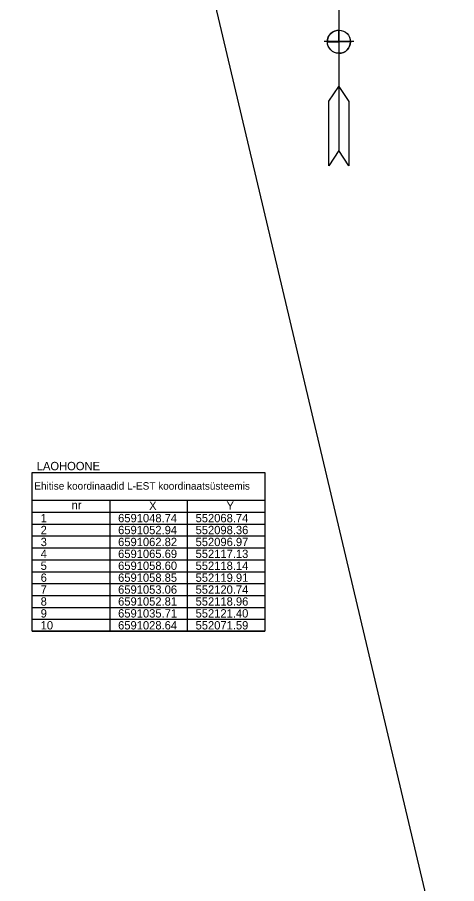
# Model space of a CAD drawing. Extents: x 551828 to 552309, y 6590593 to 6591152.
# Drawn here: x 552174 to 552210.9, y 6591016.3 to 6591089 of the extents above; entities that cross this region are included whole.
import ezdxf

# ---------------------------------------------------------------- set-up
doc = ezdxf.new("R2010")
doc.units = 0
for name, color, linetype in [('ABIJOONIS', 7, 'Continuous'), ('PIIR', 7, 'Continuous'), ('VORMISTUS', 7, 'Continuous')]:
    doc.layers.add(name, color=color, linetype=linetype)

msp = doc.modelspace()

# ---------------------------------------------------------------- linework, layer by layer
at = {"layer": 'ABIJOONIS'}
for p, q in [((552175.279, 6591047.486), (552175.279, 6591050.82)), ((552175.279, 6591050.82), (552194.779, 6591050.82)), ((552194.779, 6591050.82), (552194.779, 6591047.486)), ((552175.279, 6591048.486), (552194.779, 6591048.486)), ((552181.779, 6591048.486), (552181.779, 6591047.486)), ((552188.279, 6591048.486), (552188.279, 6591047.486)), ((552181.779, 6591047.486), (552181.779, 6591037.486)), ((552188.279, 6591047.486), (552188.279, 6591037.486)), ((552175.279, 6591046.486), (552194.779, 6591046.486)), ((552175.279, 6591045.486), (552194.779, 6591045.486)), ((552175.279, 6591044.486), (552194.779, 6591044.486)), ((552175.279, 6591043.486), (552194.779, 6591043.486)), ((552175.279, 6591042.486), (552194.779, 6591042.486)), ((552175.279, 6591041.486), (552194.779, 6591041.486)), ((552175.279, 6591040.486), (552194.779, 6591040.486)), ((552175.279, 6591039.486), (552194.779, 6591039.486)), ((552175.279, 6591038.486), (552194.779, 6591038.486)), ((552175.279, 6591037.486), (552194.779, 6591037.486))]:
    msp.add_line(p, q, dxfattribs=at)
msp.add_lwpolyline([(552175.279, 6591047.486), (552194.779, 6591047.486), (552194.779, 6591037.486), (552175.279, 6591037.486)], close=True, dxfattribs=at)
at = {"layer": 'PIIR'}
msp.add_lwpolyline([(552143.71, 6591108.79), (552149.14, 6591087.65), (552174.83, 6590987.99), (552199.8, 6590891.16), (552215.43, 6590830.96), (552218.38, 6590819.63), (552233.09, 6590762.58), (552245.52, 6590714.43), (552247.96, 6590705.32), (552276.62, 6590593.49), (552283.18, 6590594.89), (552309.49, 6590600.56), (552291.06, 6590677.95), (552287.13, 6590694.59), (552278.69, 6590730.27), (552251.37, 6590840.7), (552224.32, 6590947.63), (552220.28, 6590964.73), (552176.02, 6591151.99)], close=True, dxfattribs=at)
at = {"layer": 'VORMISTUS'}
msp.add_line((552202.268, 6591086.998), (552199.766, 6591087), dxfattribs=at)
for points in [[(552201.017, 6591097.414), (552200.177, 6591090.117), (552201.012, 6591091.368), (552201.005, 6591083.236), (552201.838, 6591081.984), (552201.834, 6591076.563), (552201.001, 6591077.847)], [(552200.035, 6591086.99), (552201.008, 6591086.989), (552201.009, 6591087.962)], [(552201.981, 6591086.988), (552201.008, 6591086.989), (552201.007, 6591086.016)]]:
    msp.add_lwpolyline(points, dxfattribs=at)
msp.add_lwpolyline([(552201.005, 6591083.236), (552201.001, 6591077.847), (552200.166, 6591076.564), (552200.17, 6591081.986)], close=True, dxfattribs=at)
msp.add_circle((552201.008, 6591086.989), 0.973, dxfattribs=at)
for start, end in [(89.95204, 179.95247), (269.95204, 359.95247)]:
    msp.add_arc((552201.008, 6591086.989), 0.973, start, end, dxfattribs=at)

# ---------------------------------------------------------------- texts
at = {"layer": 'ABIJOONIS'}
for s, height, p in [('LAOHOONE', 0.7, (552175.652, 6591051.006)), ('Ehitise koordinaadid L-EST koordinaatsüsteemis', 0.62713, (552175.445, 6591049.376)), ('nr', 0.7, (552178.58, 6591047.732)), ('X', 0.7, (552185.077, 6591047.673)), ('Y', 0.7, (552191.576, 6591047.682)), ('1', 0.7, (552175.979, 6591046.636)), ('6591048.74', 0.7, (552182.479, 6591046.636)), ('552068.74', 0.7, (552188.979, 6591046.636)), ('2', 0.7, (552175.979, 6591045.636)), ('6591052.94', 0.7, (552182.479, 6591045.636)), ('552098.36', 0.7, (552188.979, 6591045.636)), ('3', 0.7, (552175.979, 6591044.636)), ('6591062.82', 0.7, (552182.479, 6591044.636)), ('552096.97', 0.7, (552188.979, 6591044.636)), ('4', 0.7, (552175.979, 6591043.636)), ('6591065.69', 0.7, (552182.479, 6591043.636)), ('552117.13', 0.7, (552188.979, 6591043.636)), ('5', 0.7, (552175.979, 6591042.636)), ('6591058.60', 0.7, (552182.479, 6591042.636)), ('552118.14', 0.7, (552188.979, 6591042.636)), ('6', 0.7, (552175.979, 6591041.636)), ('6591058.85', 0.7, (552182.479, 6591041.636)), ('552119.91', 0.7, (552188.979, 6591041.636)), ('7', 0.7, (552175.979, 6591040.636)), ('6591053.06', 0.7, (552182.479, 6591040.636)), ('552120.74', 0.7, (552188.979, 6591040.636)), ('8', 0.7, (552175.979, 6591039.636)), ('6591052.81', 0.7, (552182.479, 6591039.636)), ('552118.96', 0.7, (552188.979, 6591039.636)), ('9', 0.7, (552175.979, 6591038.636)), ('6591035.71', 0.7, (552182.479, 6591038.636)), ('552121.40', 0.7, (552188.979, 6591038.636)), ('10', 0.7, (552175.979, 6591037.636)), ('6591028.64', 0.7, (552182.479, 6591037.636)), ('552071.59', 0.7, (552188.979, 6591037.636))]:
    msp.add_text(s, height=height, dxfattribs=at).set_placement(p)

doc.saveas('drawing.dxf')
